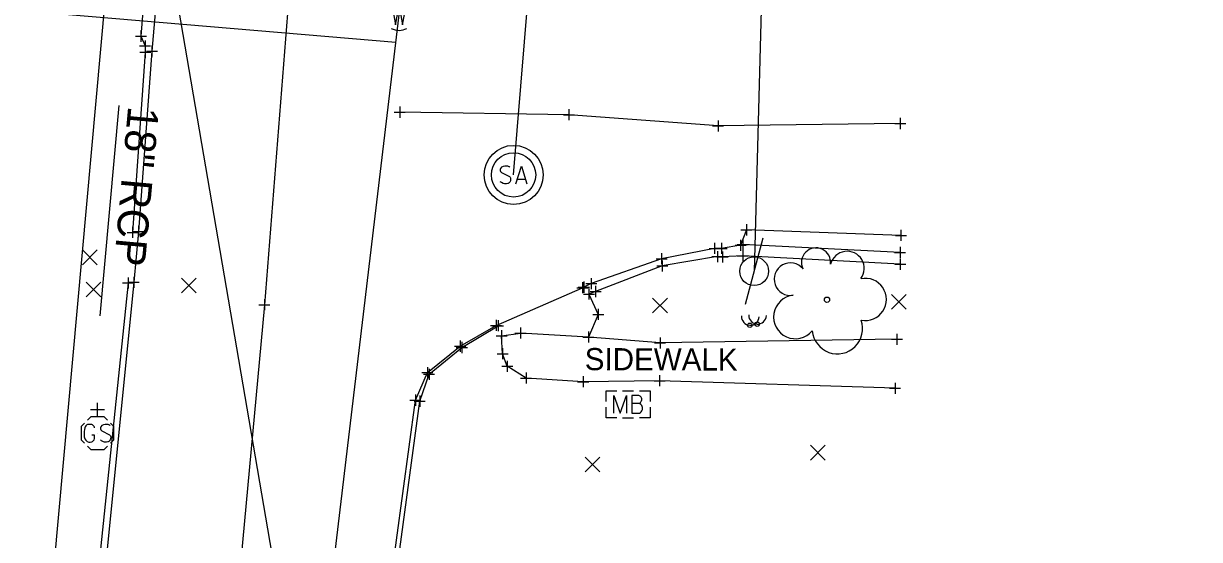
# Model space of a CAD drawing. Extents: x 1380440 to 1381945, y 468756 to 470369.
# Drawn here: x 1381508.5 to 1381614.9, y 469112.5 to 469159.2 of the extents above; entities that cross this region are included whole.
import ezdxf

# ---------------------------------------------------------------- set-up
doc = ezdxf.new("R2010")
doc.units = 0
for name, color, linetype in [('DR_P_Headwall', 7, 'Continuous'), ('DR_X_Cells', 7, 'Continuous'), ('GE_P_Driveway_CL', 7, 'Continuous'), ('PM_P_Crosswalk', 7, 'Continuous'), ('PM_X_CL_Double_Solid', 7, 'Continuous'), ('PV_P_Curb_Ramp', 7, 'Continuous'), ('PV_P_EOP', 7, 'Continuous'), ('PV_X_COP', 7, 'Continuous'), ('RD_P_Cells', 7, 'Continuous'), ('RW_P_Const_Limits', 7, 'Continuous'), ('RW_P_Esmt_TMP', 7, 'Continuous'), ('RW_X_CL', 7, 'Continuous'), ('RW_X_Esmt_SH', 7, 'Continuous'), ('SC_Scratch10', 7, 'Continuous'), ('SC_Shading1', 7, 'Continuous'), ('SH_Named_Boundary', 7, 'Continuous'), ('UT_X_Gas_Cells', 7, 'Continuous'), ('UT_X_Overhead_Combined', 7, 'Continuous'), ('UT_X_Overhead_Telecom', 7, 'Continuous'), ('UT_X_Sanitary_Line', 7, 'Continuous'), ('UT_X_Water', 7, 'Continuous'), ('X-CL', 7, 'Continuous'), ('X-SUBDIVISION', 7, 'Continuous')]:
    doc.layers.add(name, color=color, linetype=linetype)

msp = doc.modelspace()

# ---------------------------------------------------------------- linework, layer by layer
at = {"layer": 'DR_P_Headwall'}
for points in [[(1381587.36, 469126.2), (1381566.06, 469126.87), (1381559.15, 469126.79), (1381553.99, 469127.12), (1381552.29, 469128.18), (1381551.86, 469129.31), (1381551.77, 469130.94), (1381553.48, 469131.18)], [(1381587.53, 469130.62), (1381566.11, 469130.29), (1381559.63, 469130.82), (1381553.48, 469131.18)]]:
    msp.add_lwpolyline(points, dxfattribs=at)
at = {"layer": 'DR_X_Cells'}
for points in [[(1381519.54, 469157.13), (1381519.55, 469156.55), (1381518.4, 469140.28)], [(1381587.81, 469138.47), (1381573.59, 469139.18), (1381573.39, 469139.11)], [(1381587.83, 469137.41), (1381573.58, 469138.17), (1381571.75, 469138.06), (1381571.29, 469138.09), (1381566.3, 469137.25), (1381560.28, 469134.94), (1381559.67, 469134.71)], [(1381518, 469135.71), (1381515.36, 469110.2), (1381515.44, 469109.41)]]:
    msp.add_lwpolyline(points, dxfattribs=at)
at = {"layer": 'GE_P_Driveway_CL'}
for p, q in [((1381513.87, 469137.36), (1381515.21, 469138.7)), ((1381513.87, 469138.7), (1381515.21, 469137.36)), ((1381522.82, 469134.81), (1381524.15, 469136.14)), ((1381522.82, 469136.14), (1381524.15, 469134.81)), ((1381514.2, 469134.45), (1381515.54, 469135.78)), ((1381514.2, 469135.78), (1381515.54, 469134.45)), ((1381565.43, 469133.01), (1381566.77, 469134.34)), ((1381565.43, 469134.34), (1381566.77, 469133.01)), ((1381587.03, 469133.34), (1381588.37, 469134.68)), ((1381587.03, 469134.68), (1381588.37, 469133.34)), ((1381579.7, 469119.71), (1381581.03, 469121.04)), ((1381579.7, 469121.04), (1381581.03, 469119.71)), ((1381559.33, 469118.63), (1381560.66, 469119.96)), ((1381559.33, 469119.96), (1381560.66, 469118.63))]:
    msp.add_line(p, q, dxfattribs=at)
at = {"layer": 'PM_P_Crosswalk'}
msp.add_line((1381575.41, 469139.77), (1381573.8, 469133.77), dxfattribs=at)
msp.add_circle((1381574.61, 469136.77), 1.3, dxfattribs=at)
at = {"layer": 'PM_X_CL_Double_Solid'}
msp.add_lwpolyline([(1381555.39, 469442.03), (1381550.97, 469391.02), (1381547.28, 469345.9), (1381541.95, 469289.55), (1381537.19, 469231.27), (1381533.05, 469168.09), (1381530.32, 469133.74), (1381523.97, 469065.08), (1381520.12, 469021.37), (1381518.18, 469001.31)], dxfattribs=at)
at = {"layer": 'PV_P_Curb_Ramp'}
for p, q in [((1381552.86, 469147.47), (1381552.86, 469147.47)), ((1381552.86, 469145.47), (1381552.86, 469145.47)), ((1381552.86, 469145.47), (1381552.86, 469145.47)), ((1381552.86, 469145.47), (1381552.86, 469145.47)), ((1381552.86, 469143.47), (1381552.86, 469143.47))]:
    msp.add_line(p, q, dxfattribs=at)
msp.add_circle((1381552.86, 469145.47), 2, dxfattribs=at)
at = {"layer": 'PV_P_EOP'}
for points in [[(1381552.53, 469146.16), (1381552.5, 469146.19), (1381552.46, 469146.21), (1381552.35, 469146.25), (1381552.21, 469146.27), (1381552.11, 469146.27), (1381552.07, 469146.27), (1381551.91, 469146.24), (1381551.77, 469146.16), (1381551.68, 469146.06), (1381551.66, 469145.96), (1381551.66, 469145.88), (1381551.68, 469145.78), (1381551.78, 469145.69), (1381552.48, 469145.32), (1381552.54, 469145.27), (1381552.57, 469145.22), (1381552.59, 469145.14), (1381552.59, 469145.06), (1381552.58, 469144.99), (1381552.57, 469144.94), (1381552.54, 469144.88), (1381552.51, 469144.83), (1381552.49, 469144.79), (1381552.45, 469144.75), (1381552.41, 469144.72), (1381552.36, 469144.7), (1381552.33, 469144.69), (1381552.21, 469144.67), (1381552.04, 469144.67), (1381551.92, 469144.7), (1381551.76, 469144.79), (1381551.66, 469144.86)], [(1381553.07, 469144.67), (1381553.57, 469146.27), (1381554.06, 469144.67)], [(1381553.94, 469145.05), (1381553.2, 469145.05)]]:
    msp.add_lwpolyline(points, dxfattribs=at)
for radius in [2.67, 2]:
    msp.add_circle((1381552.86, 469145.47), radius, dxfattribs=at)
at = {"layer": 'PV_X_COP'}
for centre in [(1381574.22, 469131.89), (1381574.89, 469131.99)]:
    msp.add_circle(centre, 0.2, dxfattribs=at)
for centre, start, end in [((1381574.26, 469132.69), 177.296, 357.296), ((1381574.92, 469132.79), 177.544, 357.544)]:
    msp.add_arc(centre, 0.8, start, end, dxfattribs=at)
at = {"layer": 'RD_P_Cells'}
for p, q in [((1381562.71, 469125.97), (1381563.71, 469125.97)), ((1381563.22, 469124.75), (1381563.22, 469124.75)), ((1381562.71, 469123.53), (1381563.71, 469123.53))]:
    msp.add_line(p, q, dxfattribs=at)
for points in [[(1381561.22, 469125), (1381561.22, 469125.97), (1381562.19, 469125.97)], [(1381561.93, 469123.95), (1381561.93, 469125.55), (1381562.51, 469123.95), (1381563.06, 469125.55), (1381563.06, 469123.95)], [(1381564.24, 469124.82), (1381564.31, 469124.88), (1381564.34, 469124.92), (1381564.37, 469124.96), (1381564.38, 469124.98), (1381564.41, 469125.03), (1381564.42, 469125.07), (1381564.45, 469125.16), (1381564.45, 469125.19), (1381564.45, 469125.25), (1381564.43, 469125.32), (1381564.41, 469125.38), (1381564.37, 469125.43), (1381564.31, 469125.48), (1381564.26, 469125.51), (1381564.23, 469125.52), (1381564.17, 469125.55), (1381563.55, 469125.55), (1381563.55, 469123.95), (1381564.24, 469123.95), (1381564.33, 469124), (1381564.41, 469124.06), (1381564.47, 469124.16), (1381564.51, 469124.27), (1381564.52, 469124.39), (1381564.52, 469124.46), (1381564.5, 469124.54), (1381564.45, 469124.65), (1381564.38, 469124.73), (1381564.24, 469124.82), (1381563.55, 469124.82)], [(1381564.23, 469125.97), (1381565.22, 469125.97), (1381565.22, 469125)], [(1381562.19, 469123.53), (1381561.22, 469123.53), (1381561.22, 469124.5)], [(1381565.22, 469124.5), (1381565.22, 469123.53), (1381564.23, 469123.53)]]:
    msp.add_lwpolyline(points, dxfattribs=at)
at = {"layer": 'RW_P_Const_Limits'}
msp.add_lwpolyline([(1381541.87, 469160.75), (1381542.19, 469159.02), (1381542.5, 469160.75), (1381542.82, 469159.02), (1381543.14, 469160.75)], dxfattribs=at)
msp.add_arc((1381542.5, 469159.93), 1.4, 239.9843, 299.9816, dxfattribs=at)
at = {"layer": 'RW_P_Esmt_TMP'}
for points in [[(1381529.3, 469267.44), (1381526.47, 469232.31), (1381523.61, 469197.35), (1381523.61, 469196.13), (1381521.19, 469168.77), (1381520.16, 469156.66), (1381518.94, 469140.36), (1381518.51, 469135.77), (1381515.95, 469110.14), (1381515.91, 469109.22), (1381513.99, 469088.5), (1381512.04, 469066.8), (1381509.95, 469044.61), (1381509.76, 469043.72), (1381507.94, 469023.87), (1381507.81, 469022.45), (1381506.02, 469002.56)], [(1381587.89, 469140.01), (1381573.91, 469140.51), (1381573.39, 469139.11), (1381571.66, 469138.83), (1381571.03, 469138.83), (1381566.24, 469137.9), (1381559.88, 469135.65), (1381559.21, 469135.33)], [(1381558.32, 469060.89), (1381542.74, 469061.71), (1381539.22, 469061.5), (1381536.63, 469060.42), (1381535.51, 469061.29), (1381538.22, 469081.26), (1381541.7, 469108.24), (1381543.98, 469125.12), (1381545.06, 469127.61), (1381548.03, 469130), (1381551.28, 469131.88), (1381559.09, 469135.28)], [(1381559.67, 469134.71), (1381560.52, 469132.87), (1381559.63, 469130.82), (1381553.48, 469131.18)], [(1381535.75, 469061.36), (1381538.44, 469081.27), (1381542.11, 469108.32), (1381544.37, 469125.03), (1381545.21, 469127.46), (1381548.18, 469129.88), (1381551.46, 469131.85)], [(1381587.36, 469126.2), (1381566.06, 469126.87), (1381559.15, 469126.79), (1381553.99, 469127.12), (1381552.29, 469128.18), (1381551.86, 469129.31), (1381551.77, 469130.94), (1381553.48, 469131.18)]]:
    msp.add_lwpolyline(points, dxfattribs=at)
at = {"layer": 'RW_X_CL'}
msp.add_line((1381515.48, 469132.74), (1381517.19, 469151.75), dxfattribs=at)
at = {"layer": 'RW_X_Esmt_SH'}
msp.add_lwpolyline([(1381487.83, 469171.67), (1381488.59, 469175.57), (1381489.8, 469177.06), (1381491.8, 469178.46), (1381493.74, 469178.7), (1381500, 469178.74), (1381505.25, 469177.97), (1381510.63, 469175.94), (1381513.75, 469175.08), (1381519.99, 469168.46), (1381519.16, 469158.01), (1381519.54, 469157.13)], dxfattribs=at)
at = {"layer": 'SC_Scratch10'}
msp.add_circle((1381581.2, 469134.19), 0.24, dxfattribs=at)
for centre, radius, start, end in [((1381580.21, 469137.56), 1.32, 354.0047, 205.9741), ((1381583.02, 469137.02), 1.55, 323.83, 165.0376), ((1381577.89, 469136.05), 1.47, 39.0625, 279.5412), ((1381584.66, 469134.22), 1.91, 259.1453, 101.4596), ((1381578.34, 469132.64), 1.97, 96.1722, 320.5737), ((1381582.14, 469131.58), 2.28, 184.9476, 19.4572)]:
    msp.add_arc(centre, radius, start, end, dxfattribs=at)
at = {"layer": 'SC_Shading1'}
for points in [[(1381555.39, 469442.03), (1381550.97, 469391.02), (1381547.28, 469345.9), (1381541.95, 469289.55), (1381537.19, 469231.27), (1381533.05, 469168.09), (1381530.32, 469133.74), (1381523.97, 469065.08), (1381520.12, 469021.37), (1381518.18, 469001.31)], [(1381587.82, 469150.12), (1381571.35, 469149.9), (1381557.86, 469150.91), (1381542.56, 469151.14)]]:
    msp.add_lwpolyline(points, dxfattribs=at)
at = {"layer": 'SH_Named_Boundary'}
for p, q in [((1381519.16, 469158.51), (1381519.16, 469157.51)), ((1381518.66, 469158.01), (1381519.66, 469158.01)), ((1381519.16, 469158.01), (1381519.16, 469158.01)), ((1381519.54, 469157.63), (1381519.54, 469156.63)), ((1381519.54, 469157.63), (1381519.54, 469156.63)), ((1381519.04, 469157.13), (1381520.04, 469157.13)), ((1381519.04, 469157.13), (1381520.04, 469157.13)), ((1381519.05, 469156.55), (1381520.05, 469156.55)), ((1381519.54, 469157.13), (1381519.54, 469157.13)), ((1381519.54, 469157.13), (1381519.54, 469157.13)), ((1381519.55, 469157.05), (1381519.55, 469156.05)), ((1381519.55, 469156.55), (1381519.55, 469156.55)), ((1381519.66, 469156.66), (1381520.66, 469156.66)), ((1381520.16, 469157.16), (1381520.16, 469156.16)), ((1381520.16, 469156.66), (1381520.16, 469156.66)), ((1381542.06, 469151.14), (1381543.06, 469151.14)), ((1381542.56, 469151.64), (1381542.56, 469150.64)), ((1381542.56, 469151.14), (1381542.56, 469151.14)), ((1381557.86, 469151.41), (1381557.86, 469150.41)), ((1381557.36, 469150.91), (1381558.36, 469150.91)), ((1381557.86, 469150.91), (1381557.86, 469150.91)), ((1381571.35, 469150.4), (1381571.35, 469149.4)), ((1381587.32, 469150.12), (1381588.32, 469150.12)), ((1381587.82, 469150.62), (1381587.82, 469149.62)), ((1381587.82, 469150.12), (1381587.82, 469150.12)), ((1381570.85, 469149.9), (1381571.85, 469149.9)), ((1381571.35, 469149.9), (1381571.35, 469149.9)), ((1381518.4, 469140.78), (1381518.4, 469139.78)), ((1381518.44, 469140.36), (1381519.44, 469140.36)), ((1381518.94, 469140.86), (1381518.94, 469139.86)), ((1381518.94, 469140.36), (1381518.94, 469140.36)), ((1381573.41, 469140.51), (1381574.41, 469140.51)), ((1381573.91, 469141.01), (1381573.91, 469140.01)), ((1381573.91, 469140.51), (1381573.91, 469140.51)), ((1381587.89, 469140.51), (1381587.89, 469139.51)), ((1381517.9, 469140.28), (1381518.9, 469140.28)), ((1381518.4, 469140.28), (1381518.4, 469140.28)), ((1381571.03, 469139.33), (1381571.03, 469138.33)), ((1381571.03, 469139.33), (1381571.03, 469138.33)), ((1381571.66, 469139.33), (1381571.66, 469138.33)), ((1381573.39, 469139.61), (1381573.39, 469138.61)), ((1381573.39, 469139.61), (1381573.39, 469138.61)), ((1381573.59, 469139.68), (1381573.59, 469138.68)), ((1381587.39, 469140.01), (1381588.39, 469140.01)), ((1381587.89, 469140.01), (1381587.89, 469140.01)), ((1381566.24, 469138.4), (1381566.24, 469137.4)), ((1381570.53, 469138.83), (1381571.53, 469138.83)), ((1381570.53, 469138.83), (1381571.53, 469138.83)), ((1381571.03, 469138.83), (1381571.03, 469138.83)), ((1381571.03, 469138.83), (1381571.03, 469138.83)), ((1381571.16, 469138.83), (1381572.16, 469138.83)), ((1381571.29, 469138.59), (1381571.29, 469137.59)), ((1381571.29, 469138.59), (1381571.29, 469137.59)), ((1381571.66, 469138.83), (1381571.66, 469138.83)), ((1381571.75, 469138.56), (1381571.75, 469137.56)), ((1381572.89, 469139.11), (1381573.89, 469139.11)), ((1381572.89, 469139.11), (1381573.89, 469139.11)), ((1381573.09, 469139.18), (1381574.09, 469139.18)), ((1381573.39, 469139.11), (1381573.39, 469139.11)), ((1381573.39, 469139.11), (1381573.39, 469139.11)), ((1381573.58, 469138.67), (1381573.58, 469137.67)), ((1381573.59, 469139.18), (1381573.59, 469139.18)), ((1381587.31, 469138.47), (1381588.31, 469138.47)), ((1381587.81, 469138.97), (1381587.81, 469137.97)), ((1381587.81, 469138.47), (1381587.81, 469138.47)), ((1381565.74, 469137.9), (1381566.74, 469137.9)), ((1381565.8, 469137.25), (1381566.8, 469137.25)), ((1381566.24, 469137.9), (1381566.24, 469137.9)), ((1381566.3, 469137.75), (1381566.3, 469136.75)), ((1381566.3, 469137.25), (1381566.3, 469137.25)), ((1381570.79, 469138.09), (1381571.79, 469138.09)), ((1381570.79, 469138.09), (1381571.79, 469138.09)), ((1381571.25, 469138.06), (1381572.25, 469138.06)), ((1381571.29, 469138.09), (1381571.29, 469138.09)), ((1381571.29, 469138.09), (1381571.29, 469138.09)), ((1381571.75, 469138.06), (1381571.75, 469138.06)), ((1381573.08, 469138.17), (1381574.08, 469138.17)), ((1381573.58, 469138.17), (1381573.58, 469138.17)), ((1381587.33, 469137.41), (1381588.33, 469137.41)), ((1381587.83, 469137.91), (1381587.83, 469136.91)), ((1381587.83, 469137.41), (1381587.83, 469137.41)), ((1381518, 469136.21), (1381518, 469135.21)), ((1381518.51, 469136.27), (1381518.51, 469135.27)), ((1381559.88, 469136.15), (1381559.88, 469135.15)), ((1381559.88, 469136.15), (1381559.88, 469135.15)), ((1381517.5, 469135.71), (1381518.5, 469135.71)), ((1381518, 469135.71), (1381518, 469135.71)), ((1381518.01, 469135.77), (1381519.01, 469135.77)), ((1381518.51, 469135.77), (1381518.51, 469135.77)), ((1381558.59, 469135.28), (1381559.59, 469135.28)), ((1381558.71, 469135.33), (1381559.71, 469135.33)), ((1381559.09, 469135.78), (1381559.09, 469134.78)), ((1381559.09, 469135.28), (1381559.09, 469135.28)), ((1381559.21, 469135.83), (1381559.21, 469134.83)), ((1381559.21, 469135.33), (1381559.21, 469135.33)), ((1381559.38, 469135.65), (1381560.38, 469135.65)), ((1381559.38, 469135.65), (1381560.38, 469135.65)), ((1381559.67, 469135.21), (1381559.67, 469134.21)), ((1381559.67, 469135.21), (1381559.67, 469134.21)), ((1381559.88, 469135.65), (1381559.88, 469135.65)), ((1381559.88, 469135.65), (1381559.88, 469135.65)), ((1381560.28, 469135.44), (1381560.28, 469134.44)), ((1381560.28, 469135.44), (1381560.28, 469134.44)), ((1381530.32, 469134.24), (1381530.32, 469133.24)), ((1381559.17, 469134.71), (1381560.17, 469134.71)), ((1381559.17, 469134.71), (1381560.17, 469134.71)), ((1381559.67, 469134.71), (1381559.67, 469134.71)), ((1381559.67, 469134.71), (1381559.67, 469134.71)), ((1381559.78, 469134.94), (1381560.78, 469134.94)), ((1381559.78, 469134.94), (1381560.78, 469134.94)), ((1381560.28, 469134.94), (1381560.28, 469134.94)), ((1381560.28, 469134.94), (1381560.28, 469134.94)), ((1381529.82, 469133.74), (1381530.82, 469133.74)), ((1381530.32, 469133.74), (1381530.32, 469133.74)), ((1381560.52, 469133.37), (1381560.52, 469132.37)), ((1381550.78, 469131.88), (1381551.78, 469131.88)), ((1381550.96, 469131.85), (1381551.96, 469131.85)), ((1381551.28, 469132.38), (1381551.28, 469131.38)), ((1381551.28, 469131.88), (1381551.28, 469131.88)), ((1381551.46, 469132.35), (1381551.46, 469131.35)), ((1381551.46, 469131.85), (1381551.46, 469131.85)), ((1381560.02, 469132.87), (1381561.02, 469132.87)), ((1381560.52, 469132.87), (1381560.52, 469132.87)), ((1381551.27, 469130.94), (1381552.27, 469130.94)), ((1381551.27, 469130.94), (1381552.27, 469130.94)), ((1381551.77, 469131.44), (1381551.77, 469130.44)), ((1381551.77, 469131.44), (1381551.77, 469130.44)), ((1381551.77, 469130.94), (1381551.77, 469130.94)), ((1381551.77, 469130.94), (1381551.77, 469130.94)), ((1381552.98, 469131.18), (1381553.98, 469131.18)), ((1381552.98, 469131.18), (1381553.98, 469131.18)), ((1381552.98, 469131.18), (1381553.98, 469131.18)), ((1381552.98, 469131.18), (1381553.98, 469131.18)), ((1381553.48, 469131.68), (1381553.48, 469130.68)), ((1381553.48, 469131.68), (1381553.48, 469130.68)), ((1381553.48, 469131.68), (1381553.48, 469130.68)), ((1381553.48, 469131.68), (1381553.48, 469130.68)), ((1381553.48, 469131.18), (1381553.48, 469131.18)), ((1381553.48, 469131.18), (1381553.48, 469131.18)), ((1381553.48, 469131.18), (1381553.48, 469131.18)), ((1381553.48, 469131.18), (1381553.48, 469131.18)), ((1381559.13, 469130.82), (1381560.13, 469130.82)), ((1381559.13, 469130.82), (1381560.13, 469130.82)), ((1381559.63, 469131.32), (1381559.63, 469130.32)), ((1381559.63, 469131.32), (1381559.63, 469130.32)), ((1381559.63, 469130.82), (1381559.63, 469130.82)), ((1381559.63, 469130.82), (1381559.63, 469130.82)), ((1381566.11, 469130.79), (1381566.11, 469129.79)), ((1381587.53, 469131.12), (1381587.53, 469130.12)), ((1381547.53, 469130), (1381548.53, 469130)), ((1381547.68, 469129.88), (1381548.68, 469129.88)), ((1381548.03, 469130.5), (1381548.03, 469129.5)), ((1381548.03, 469130), (1381548.03, 469130)), ((1381548.18, 469130.38), (1381548.18, 469129.38)), ((1381548.18, 469129.88), (1381548.18, 469129.88)), ((1381551.86, 469129.81), (1381551.86, 469128.81)), ((1381551.86, 469129.81), (1381551.86, 469128.81)), ((1381565.61, 469130.29), (1381566.61, 469130.29)), ((1381566.11, 469130.29), (1381566.11, 469130.29)), ((1381587.03, 469130.62), (1381588.03, 469130.62)), ((1381587.53, 469130.62), (1381587.53, 469130.62)), ((1381551.36, 469129.31), (1381552.36, 469129.31)), ((1381551.36, 469129.31), (1381552.36, 469129.31)), ((1381551.86, 469129.31), (1381551.86, 469129.31)), ((1381551.86, 469129.31), (1381551.86, 469129.31)), ((1381552.29, 469128.68), (1381552.29, 469127.68)), ((1381552.29, 469128.68), (1381552.29, 469127.68)), ((1381544.56, 469127.61), (1381545.56, 469127.61)), ((1381545.06, 469128.11), (1381545.06, 469127.11)), ((1381545.06, 469127.61), (1381545.06, 469127.61)), ((1381545.21, 469127.96), (1381545.21, 469126.96)), ((1381551.79, 469128.18), (1381552.79, 469128.18)), ((1381551.79, 469128.18), (1381552.79, 469128.18)), ((1381552.29, 469128.18), (1381552.29, 469128.18)), ((1381552.29, 469128.18), (1381552.29, 469128.18)), ((1381553.99, 469127.62), (1381553.99, 469126.62)), ((1381553.99, 469127.62), (1381553.99, 469126.62)), ((1381544.71, 469127.46), (1381545.71, 469127.46)), ((1381545.21, 469127.46), (1381545.21, 469127.46)), ((1381553.49, 469127.12), (1381554.49, 469127.12)), ((1381553.49, 469127.12), (1381554.49, 469127.12)), ((1381553.99, 469127.12), (1381553.99, 469127.12)), ((1381553.99, 469127.12), (1381553.99, 469127.12)), ((1381558.65, 469126.79), (1381559.65, 469126.79)), ((1381558.65, 469126.79), (1381559.65, 469126.79)), ((1381559.15, 469127.29), (1381559.15, 469126.29)), ((1381559.15, 469127.29), (1381559.15, 469126.29)), ((1381559.15, 469126.79), (1381559.15, 469126.79)), ((1381559.15, 469126.79), (1381559.15, 469126.79)), ((1381565.56, 469126.87), (1381566.56, 469126.87)), ((1381565.56, 469126.87), (1381566.56, 469126.87)), ((1381566.06, 469127.37), (1381566.06, 469126.37)), ((1381566.06, 469127.37), (1381566.06, 469126.37)), ((1381566.06, 469126.87), (1381566.06, 469126.87)), ((1381566.06, 469126.87), (1381566.06, 469126.87)), ((1381587.36, 469126.7), (1381587.36, 469125.7)), ((1381587.36, 469126.7), (1381587.36, 469125.7)), ((1381543.98, 469125.62), (1381543.98, 469124.62)), ((1381544.37, 469125.53), (1381544.37, 469124.53)), ((1381586.86, 469126.2), (1381587.86, 469126.2)), ((1381586.86, 469126.2), (1381587.86, 469126.2)), ((1381587.36, 469126.2), (1381587.36, 469126.2)), ((1381587.36, 469126.2), (1381587.36, 469126.2)), ((1381543.48, 469125.12), (1381544.48, 469125.12)), ((1381543.87, 469125.03), (1381544.87, 469125.03)), ((1381543.98, 469125.12), (1381543.98, 469125.12)), ((1381544.37, 469125.03), (1381544.37, 469125.03))]:
    msp.add_line(p, q, dxfattribs=at)
at = {"layer": 'UT_X_Gas_Cells'}
for p, q in [((1381515.23, 469123.62), (1381515.23, 469124.89)), ((1381515.87, 469124.25), (1381514.59, 469124.25)), ((1381515.23, 469122.13), (1381515.23, 469122.13))]:
    msp.add_line(p, q, dxfattribs=at)
for points in [[(1381516.13, 469123.31), (1381515.82, 469123.62), (1381514.64, 469123.62), (1381514.34, 469123.31)], [(1381514.06, 469123.03), (1381513.75, 469122.73), (1381513.75, 469121.54), (1381514.05, 469121.24)], [(1381514.97, 469122.62), (1381514.96, 469122.68), (1381514.92, 469122.75), (1381514.86, 469122.81), (1381514.77, 469122.88), (1381514.71, 469122.91), (1381514.66, 469122.92), (1381514.58, 469122.93), (1381514.43, 469122.93), (1381514.37, 469122.92), (1381514.33, 469122.91), (1381514.28, 469122.88), (1381514.18, 469122.81), (1381514.12, 469122.72), (1381514.08, 469122.62), (1381514.06, 469122.48), (1381514.03, 469122.28), (1381514.03, 469122.02), (1381514.04, 469121.8), (1381514.09, 469121.64), (1381514.17, 469121.49), (1381514.23, 469121.44), (1381514.31, 469121.39), (1381514.45, 469121.33), (1381514.58, 469121.33), (1381514.72, 469121.36), (1381514.77, 469121.39), (1381514.82, 469121.41), (1381514.87, 469121.46), (1381514.92, 469121.54), (1381514.97, 469121.65), (1381514.97, 469121.96), (1381514.71, 469121.96)], [(1381516.37, 469122.82), (1381516.35, 469122.85), (1381516.31, 469122.87), (1381516.2, 469122.91), (1381516.06, 469122.93), (1381515.96, 469122.93), (1381515.92, 469122.93), (1381515.76, 469122.9), (1381515.62, 469122.82), (1381515.53, 469122.72), (1381515.5, 469122.62), (1381515.5, 469122.54), (1381515.53, 469122.44), (1381515.63, 469122.36), (1381516.32, 469121.98), (1381516.39, 469121.93), (1381516.41, 469121.88), (1381516.44, 469121.8), (1381516.44, 469121.73), (1381516.42, 469121.65), (1381516.41, 469121.6), (1381516.39, 469121.54), (1381516.36, 469121.49), (1381516.34, 469121.45), (1381516.3, 469121.41), (1381516.26, 469121.39), (1381516.21, 469121.36), (1381516.17, 469121.35), (1381516.06, 469121.33), (1381515.88, 469121.33), (1381515.77, 469121.36), (1381515.6, 469121.45), (1381515.5, 469121.52)], [(1381516.41, 469121.24), (1381516.71, 469121.54), (1381516.71, 469122.73), (1381516.41, 469123.03)], [(1381514.33, 469120.96), (1381514.64, 469120.65), (1381515.82, 469120.65), (1381516.13, 469120.96)]]:
    msp.add_lwpolyline(points, dxfattribs=at)
at = {"layer": 'UT_X_Overhead_Combined'}
msp.add_lwpolyline([(1381540.8, 469054.26), (1381515.28, 469203.1), (1381529.17, 469390.12), (1381543.86, 469565.78), (1381559.77, 469757.41), (1381571.97, 469887.64), (1381581.26, 470018.2), (1381595.79, 470220.83), (1381665.56, 470247.4)], dxfattribs=at)
at = {"layer": 'UT_X_Overhead_Telecom'}
msp.add_line((1381575.35, 469164.51), (1381574.61, 469136.77), dxfattribs=at)
at = {"layer": 'UT_X_Sanitary_Line'}
msp.add_line((1381552.86, 469145.47), (1381576.01, 469430.09), dxfattribs=at)
at = {"layer": 'UT_X_Water'}
for p, q in [((1381542.21, 469157.44), (1381472.47, 469163.31)), ((1381527.44, 469033.4), (1381542.5, 469159.93))]:
    msp.add_line(p, q, dxfattribs=at)
at = {"layer": 'X-CL'}
msp.add_line((1381528.04, 469296.45), (1381500.71, 468992.41), dxfattribs=at)

# ---------------------------------------------------------------- texts
at = {"layer": 'RW_X_CL'}
msp.add_text('18" RCP', height=2.8, rotation=264.8634, dxfattribs=at).set_placement((1381518.01, 469151.74))
at = {"layer": 'X-SUBDIVISION'}
msp.add_text('SIDEWALK', height=2, rotation=359.8186, dxfattribs=at).set_placement((1381559.29, 469127.83))

doc.saveas('drawing.dxf')
